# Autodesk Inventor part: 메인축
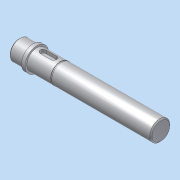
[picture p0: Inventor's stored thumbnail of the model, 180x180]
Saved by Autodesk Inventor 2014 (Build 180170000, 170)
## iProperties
Company: 한국ATC센터
Created: 2014-12
Part Number: 메인축
Document SubType Name: Modeling
Designer: KYOUNG IL JANG
Density: 1 g/cm^3
Mass: 27.2374 g
Surface Area: 71.2962 cm^2
Volume: 27.2374 cm^3
Material: 일반
Appearance: 기본값
Author: KYOUNG IL JANG
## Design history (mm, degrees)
sketch "스케치1"
  geometry: L1 (0, 0)-(120, 0); L2 (0, 0)-(0, 7.5); L3 (1, 8.5)-(12, 8.5); L4 (12, 8.5)-(12, 10); L5 (12, 10)-(15, 10); L6 (15, 10)-(15, 8.5); L7 (15, 8.5)-(119, 8.5); L8 (120, 0)-(120, 7.5); L9 (1, 8.5)-(0, 7.5); L10 (119, 8.5)-(120, 7.5); 2 further points
  constraints: 20 end point, 4 point on line, 3 parallel, 3 perpendicular, 1 collinear, 1 horizontal
  dimensions: "d0" = 12 distance of point (0, 8.5) L3.end; "d1" = 17 diameter of L3 L1; "d2" = 20 diameter of L5 L1; "d3" = 17 diameter of L7 L1; "d4" = 3 distance of L4.end L5.end; "d5" = 120 distance of L1.start L1.end; "d6" = 1 distance of L3.start point (0, 8.5); "d7" = 1 distance of L2.end point (0, 8.5) (= d6); "d8" = 1 distance of L7.end point (120, 8.5) (= d6); "d9" = 1 distance of L8.end point (120, 8.5) (= d8)
revolve "회전1" sketch "스케치1" stored, may be unused: angle "d10" = 90 deg
node "작업 평면1"
sketch "스케치2"
  geometry: L1 (-46.5, 2.5)-(-37.5, 2.5); L2 (-37.5, -2.5)-(-46.5, -2.5); L3 (-52, -10)-(-52, 10) reference; A1 r 2.5 centre (-37.5, 0) between (-37.5, -2.5) and (-37.5, 2.5); A2 r 2.5 centre (-46.5, 0) between (-46.5, 2.5) and (-46.5, -2.5); 1 further point
  constraints: 4 end point, 4 point on circle, 4 tangent, 2 centre point, 1 horizontal, 1 horizontal alignment, 1 parallel
  dimensions: "d11" = 5 distance between parallel lines of L2 L1; "d12" = 3 distance edge to line of A2 L3; "d13" = 14 dimension on A1 A2
extrude "돌출1" cut sketch "스케치2" distance "d14" = 3; taper "d15" = 0 deg
sketch "스케치3"
  geometry: L1 (15, 8.5)-(119, 8.5) reference; L2 (35, 8.5)-(36.15, 8.5); L3 (36.15, 8.5)-(36.15, 8.1); L4 (36.15, 8.1)-(35, 8.1); L5 (35, 8.1)-(35, 8.5); L6 (15, -10)-(15, 10) reference; L7 (-23.8, 0)-(142.8, 0) reference; 1 further point
  constraints: 8 end point, 2 parallel, 1 horizontal, 1 perpendicular, 1 point on line
  dimensions: "d16" = 1.15 distance of L3.end L4.end; "d17" = 20 distance between parallel lines of L5 L6; "d18" = 8.1 distance from line of L4 point (0, 0)
revolve "회전2" sketch "스케치3" stored, may be unused: angle "d19" = 90 deg
node "솔리드1"
